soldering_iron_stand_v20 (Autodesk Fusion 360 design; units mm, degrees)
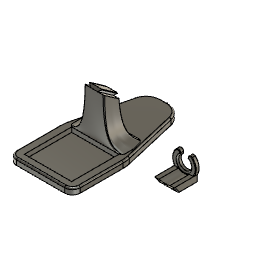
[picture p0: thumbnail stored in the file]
sketch "Sketch1" plane through (0, 0, 0) normal (0, 0, 1) x axis (1, 0, 0)
  line L1 (30.2983, -9.5) -> (-30.7017, -9.5)
  line L2 (30.2983, -70.5) -> (30.2983, -9.5)
  line L3 (-30.7017, -70.5) -> (30.2983, -70.5)
  line L4 (-30.7017, -9.5) -> (-30.7017, -70.5)
  line L5 (-31.2017, -80) -> (30.7983, -80)
  line L6 (3.9277, 80) -> (-4.3312, 80)
  line L7 (39.7519, -5.5156) -> (23.4045, 64.5446)
  line L8 (-23.808, 64.5446) -> (-40.1554, -5.5156)
  line L9 (40.7983, -70) -> (40.7983, -14.6048)
  line L10 (-41.2017, -14.6048) -> (-41.2017, -70)
  arc A1 centre (-4.3312, 60) radius 20 clockwise from (-23.808, 64.5446) to (-4.3312, 80)
  arc A2 centre (3.9277, 60) radius 20 clockwise from (3.9277, 80) to (23.4045, 64.5446)
  arc A3 centre (0.7983, -14.6048) radius 40 clockwise from (39.7519, -5.5156) to (40.7983, -14.6048)
  arc A4 centre (-1.2017, -14.6048) radius 40 clockwise from (-41.2017, -14.6048) to (-40.1554, -5.5156)
  arc A5 centre (-31.2017, -70) radius 10 clockwise from (-31.2017, -80) to (-41.2017, -70)
  arc A6 centre (30.7983, -70) radius 10 clockwise from (40.7983, -70) to (30.7983, -80)
  point P8 (-20.2017, 80)
  point P9 (19.7983, 80)
  point P10 (40.7983, -10)
  point P11 (-41.2017, -10)
  point P7 (-41.2017, -80)
  point P6 (40.7983, -80)
  point P2 (-30.7017, -9.5)
  point P3 (30.2983, -9.5)
  point P5 (-30.7017, -70.5)
  horizontal L1
  vertical L2
  horizontal L3
  vertical L4
  horizontal L5
  perpendicular L5 L9
  perpendicular L5 L10
  coincident P8 L6
  coincident P8 L8
  tangent L6 A1
  tangent L8 A1
  coincident P9 L6
  coincident P9 L7
  tangent L6 A2
  tangent L7 A2
  coincident P10 L7
  coincident P10 L9
  tangent L7 A3
  tangent L9 A3
  coincident P11 L8
  coincident P11 L10
  tangent L8 A4
  tangent L10 A4
  coincident P7 L5
  coincident P7 L10
  tangent L5 A5
  tangent L10 A5
  coincident P6 L5
  coincident P6 L9
  tangent L5 A6
  tangent L9 A6
  dimension "d1" distance P2 P3 = 61
  dimension "d2" distance P2 P5 = 61
  dimension "d7" distance P8 P9 = 40
  dimension "d9" distance P7 P11 = 70
  dimension "d11" distance P8 P11 = 90
  dimension "d12" distance P9 P10 = 90
  dimension "d13" distance P6 P7 = 82
  dimension "d14" distance P6 P10 = 70
  dimension "d15" distance P9 P10 = 21
  dimension "d16" radius A1 = 20
  dimension "d17" radius A2 = 20
  dimension "d18" radius A3 = 40
  dimension "d19" radius A4 = 40
  dimension "d20" radius A5 = 10
  dimension "d21" radius A6 = 10
  dimension "d22" distance L4 L10 = 10.5
  dimension "d23" distance L3 L5 = 9.5
extrude "Extrude1" new body sketch "Sketch1" along normal blind 8
fillet "Fillet1" radius 2
extrude "Extrude2" cut sketch "Sketch1" profile of L1 L2 L3 L4 along normal blind 10
sketch "Sketch2" plane through (0, 0, 0) normal (0, 0, 1) x axis (1, 0, 0)
  line L1 (35, -75) -> (-35, -75)
  line L2 (35, -5) -> (35, -75)
  line L3 (-35, -5) -> (35, -5)
  line L4 (-35, -75) -> (-35, -5)
  horizontal L1
  vertical L2
  horizontal L3
  vertical L4
extrude "Extrude3" add sketch "Sketch2" along normal blind 2
sketch "Sketch3" plane through (0, 0, 8) normal (0, 0, 1) x axis (-1, 0, 0)
  line L1 (30.7017, 9.5) -> (30.7017, 70.5)
  line L2 (-30.2983, 9.5) -> (30.7017, 9.5)
  line L3 (-30.2983, 70.5) -> (-30.2983, 9.5)
  line L4 (30.7017, 70.5) -> (-30.2983, 70.5)
  line L5 (-38.7983, 14.6048) -> (-38.7983, 70)
  line L6 (-21.4569, -64.0901) -> (-37.8043, 5.9701)
  line L7 (4.3312, -78) -> (-3.9277, -78)
  line L8 (38.2077, 5.9701) -> (21.8603, -64.0901)
  line L9 (39.2017, 70) -> (39.2017, 14.6048)
  line L10 (-30.7983, 78) -> (31.2017, 78)
  line L11 (-25.9962, -20.5) -> (26.3996, -20.5)
  line L12 (-33.7983, 4.5) -> (-33.7983, -3.3546)
  line L13 (29.2017, 9.5) -> (-28.7983, 9.5)
  line L14 (34.2017, -3.3546) -> (34.2017, 4.5)
  line L15 (-33.0709, -8.6994) -> (-30.8144, -16.8362)
  line L16 (33.4743, -8.6994) -> (31.2178, -16.8362)
  arc A1 centre (-30.7983, 70) radius 8 clockwise from (-38.7983, 70) to (-30.7983, 78)
  arc A2 centre (-0.7983, 14.6048) radius 38 clockwise from (-37.8043, 5.9701) to (-38.7983, 14.6048)
  arc A3 centre (-3.9277, -60) radius 18 clockwise from (-3.9277, -78) to (-21.4569, -64.0901)
  arc A4 centre (4.3312, -60) radius 18 clockwise from (21.8603, -64.0901) to (4.3312, -78)
  arc A5 centre (1.2017, 14.6048) radius 38 clockwise from (39.2017, 14.6048) to (38.2077, 5.9701)
  arc A6 centre (31.2017, 70) radius 8 clockwise from (31.2017, 78) to (39.2017, 70)
  arc A7 centre (-28.7983, 4.5) radius 5 clockwise from (-33.7983, 4.5) to (-28.7983, 9.5)
  arc A8 centre (29.2017, 4.5) radius 5 clockwise from (29.2017, 9.5) to (34.2017, 4.5)
  arc A9 centre (-13.7983, -3.3546) radius 20 clockwise from (-33.0709, -8.6994) to (-33.7983, -3.3546)
  arc A10 centre (14.2017, -3.3546) radius 20 clockwise from (34.2017, -3.3546) to (33.4743, -8.6994)
  arc A11 centre (-25.9962, -15.5) radius 5 clockwise from (-25.9962, -20.5) to (-30.8144, -16.8362)
  arc A12 centre (26.3996, -15.5) radius 5 clockwise from (31.2178, -16.8362) to (26.3996, -20.5)
  point P25 (-33.7983, -20.5)
  point P24 (34.2017, -20.5)
  point P26 (-33.7983, 9.5)
  point P27 (34.2017, 9.5)
  point P28 (-29.7983, -20.5)
  point P29 (30.2017, -20.5)
  horizontal L11
  vertical L12
  horizontal L13
  vertical L14
  coincident P25 L11
  coincident P25 L12
  coincident P24 L11
  coincident P24 L14
  coincident P26 L12
  coincident P26 L13
  tangent L12 A7
  tangent L13 A7
  coincident P27 L13
  coincident P27 L14
  tangent L13 A8
  tangent L14 A8
  equal A7 A8
  tangent L15 A9
  tangent L12 A9
  tangent L16 A10
  tangent L14 A10
  equal A9 A10
  coincident P28 L15
  coincident L11 P28
  tangent L15 A11
  tangent L11 A11
  coincident P29 L16
  coincident L11 P29
  tangent L16 A12
  tangent L11 A12
  equal A11 A12
  dimension "d32" distance P26 P27 = 68
  dimension "d33" distance L1 L14 = 3.5
  dimension "d34" distance P24 P27 = 30
  dimension "d35" distance L2 L11 = 30
  dimension "d36" distance P25 P28 = 4
  dimension "d37" angle L11 L15 = 74.5
  dimension "d38" distance P24 P29 = 4
  dimension "d39" angle L11 L16 = 74.5
  dimension "d40" radius A7 = 5
  dimension "d41" radius A9 = 20
  dimension "d42" radius A11 = 5
work_plane "WorkPlane1" sketch "Sketch3" AlongDistance 61
sketch "Sketch4" plane through (-0.2017, 0, 69) normal (0, 0, 1) x axis (1, 0, 0)
  line L1 (-14, -9.5) -> (11, -9.5)
  line L2 (-14, 10.5) -> (-14, -9.5)
  line L3 (11, 10.5) -> (-14, 10.5)
  line L4 (11, -9.5) -> (11, 10.5)
  line L5 (-29, -9.5) -> (29, -9.5)
  line L6 (34, -4.5) -> (34, 3.3546)
  point P2 (11, -9.5)
  point P3 (-14, -9.5)
  point P5 (11, 10.5)
  horizontal L1
  vertical L2
  horizontal L3
  vertical L4
  dimension "d44" distance P2 P3 = 25
  dimension "d45" distance P2 P5 = 20
  dimension "d47" distance L3 L5 = 20
  dimension "d48" distance L4 L6 = 23
loft "Loft2" sketch "Sketch4" + "Sketch3" Start Weight 2.5 Start TakeOff Angle 0
sketch "Sketch7" plane through (0, 0, 69) normal (0, 0, 1) x axis (-1, 0, 0)
  line L1 (15.2017, 9.5) -> (-11.7983, 9.5)
  line L2 (15.2017, -11.5) -> (15.2017, 9.5)
  line L3 (-11.7983, -11.5) -> (15.2017, -11.5)
  line L4 (-11.7983, 9.5) -> (-11.7983, -11.5)
  line L5 (-10.7983, -10.5) -> (14.2017, -10.5)
  line L6 (14.2017, 9.5) -> (-10.7983, 9.5)
  line L7 (14.2017, -10.5) -> (14.2017, 9.5)
  line L8 (-10.7983, 9.5) -> (-10.7983, -10.5)
  horizontal L1
  vertical L2
  horizontal L3
  vertical L4
  dimension "d61" distance L3 L5 = 1
  dimension "d63" distance L2 L7 = 1
  dimension "d64" distance L4 L8 = 1
  dimension "d87" distance L1 L3 = 21
extrude "Extrude7" new body sketch "Sketch7" along normal blind 15
sketch "Sketch13" plane through (-15.2017, 0, 0) normal (-1, 0, 0) x axis (0, -1, 0)
  line L1 (9.5, 69) -> (-11.5, 69)
  line L2 (9.5, 84) -> (9.5, 69)
  line L3 (-11.5, 84) -> (9.5, 84)
  line L4 (-11.5, 69) -> (-11.5, 84)
  line L5 (-10.8385, 69) -> (9.5, 69)
  line L6 (-10.8385, 54.7588) -> (-10.8385, 69)
  line L7 (9.5, 69) -> (-10.8385, 54.7588)
  point P6 (9.5, 69)
  point P7 (-10.8385, 69)
  point P8 (9.5, 69)
  coincident L1 P6
  coincident L1 P7
  coincident P6 P8
  perpendicular L1 L6
  dimension "d82" angle L5 L7 = 35
extrude "Extrude13" cut sketch "Sketch13" profile of L1 L5 L6 L7 against normal blind 27
sketch "Sketch16" plane through (-15.2017, 0, 0) normal (-1, 0, 0) x axis (0, -1, 0)
  line L1 (9.5, 69) -> (-11.5, 69)
  line L2 (9.5, 84) -> (9.5, 69)
  line L3 (-11.5, 84) -> (9.5, 84)
  line L4 (-11.5, 69) -> (-11.5, 84)
  line L5 (9.5, 84) -> (9.5, 69)
  line L6 (-1.0031, 84) -> (9.5, 69)
  line L7 (-1.0031, 84) -> (9.5, 84)
  point P3 (9.5, 69)
  point P6 (9.5, 69)
  point P4 (9.5, 84)
  point P7 (9.5, 84)
  point P8 (-1.0031, 84)
  coincident P3 P6
  coincident P4 P7
  coincident L3 P8
  dimension "d97" angle L5 L6 = 35
extrude "Extrude14" cut sketch "Sketch16" profile of L2 L3 L5 L6 L7 against normal blind 27
sketch "Sketch17" plane through (0, -38.794, 27.1638) normal (0, -0.8192, 0.5736) x axis (1, 0, 0)
  line L1 (-15.2017, 51.0725) -> (-15.2017, 69.3841)
  line L2 (11.7983, 51.0725) -> (-15.2017, 51.0725)
  line L3 (11.7983, 69.3841) -> (11.7983, 51.0725)
  line L4 (-15.2017, 69.3841) -> (11.7983, 69.3841)
  line L5 (6.7983, 51.0725) -> (-10.2017, 51.0725)
  line L6 (2.7983, 47.0725) -> (6.7983, 51.0725)
  line L7 (-6.2017, 47.0725) -> (-10.2017, 51.0725)
  line L8 (2.7983, 47.0725) -> (-6.2017, 47.0725)
  line L9 (11.7983, 51.0725) -> (-15.2017, 51.0725)
  line L10 (11.7983, 47.0725) -> (11.7983, 51.0725)
  line L11 (-15.2017, 47.0725) -> (11.7983, 47.0725)
  line L12 (-15.2017, 51.0725) -> (-15.2017, 47.0725)
  point P6 (-10.2017, 51.0725)
  point P7 (6.7983, 51.0725)
  point P3 (-15.2017, 51.0725)
  point P10 (-15.2017, 51.0725)
  point P4 (11.7983, 51.0725)
  point P9 (-6.2017, 47.0725)
  point P8 (2.7983, 47.0725)
  point P11 (11.7983, 51.0725)
  coincident L2 P6
  coincident L2 P7
  perpendicular L1 L5
  horizontal L9
  vertical L10
  horizontal L11
  vertical L12
  coincident P3 P10
  dimension "d100" distance P4 P7 = 5
  dimension "d101" distance P6 P7 = 17
  dimension "d102" angle L5 L6 = 45
  dimension "d103" angle L5 L7 = 45
  dimension "d104" distance L5 P9 = 4
  dimension "d105" distance L5 P8 = 4
  dimension "d106" distance P10 P11 = 27
  dimension "d107" distance L9 L11 = 4
extrude "Extrude15" cut sketch "Sketch17" profile of L2 L6 L7 L9 L10 L11 L12 against normal blind 28
sketch "Sketch18" plane through (0, 29.294, 41.8362) normal (0, 0.5736, 0.8192) x axis (-1, 0, 0)
  line L1 (10.2017, 47.3587) -> (10.2017, 22.8335)
  line L2 (-6.7983, 47.3587) -> (10.2017, 47.3587)
  line L3 (-6.7983, 22.8335) -> (-6.7983, 47.3587)
  curve K1 (-6.7983, 22.8335) -> (10.2017, 22.8335)
  line L4 (10.2017, 47.3587) -> (-6.7983, 47.3587)
  line L5 (10.2017, 44.5507) -> (10.2017, 47.3587)
  line L6 (-6.7983, 44.5507) -> (10.2017, 44.5507)
  line L7 (-6.7983, 47.3587) -> (-6.7983, 44.5507)
  point P4 (-6.7983, 47.3587)
  point P6 (-6.7983, 47.3587)
  point P7 (10.2017, 47.3587)
  point P9 (-6.7983, 44.5507)
  horizontal L4
  vertical L5
  horizontal L6
  vertical L7
  coincident P4 P6
  dimension "d110" distance P6 P7 = 17
  dimension "d111" distance P6 P9 = 2.808
extrude "Extrude17" cut sketch "Sketch18" profile of L1 L2 L3 L4 L5 L6 L7 against normal blind 4
sketch "Sketch22" plane through (0, 0, 0) normal (0, 0, 1) x axis (1, 0, 0)
  line L1 (103.5444, 18.6577) -> (78.5444, 18.6577)
  line L2 (103.5444, -11.6363) -> (103.5444, 18.6577)
  line L3 (78.5444, -11.6363) -> (103.5444, -11.6363)
  line L4 (78.5444, 18.6577) -> (78.5444, -11.6363)
  point P2 (78.5444, 18.6577)
  point P3 (103.5444, 18.6577)
  point P5 (78.5444, -11.6363)
  horizontal L1
  vertical L2
  horizontal L3
  vertical L4
  dimension "d122" distance P2 P3 = 25
  dimension "d123" distance P2 P5 = 30.294 (= "24.692 mm + 5.602 mm")
extrude "Extrude18" new body sketch "Sketch22" along normal blind 8
sketch "Sketch23" plane through (0, -11.6363, 0) normal (0, -1, 0) x axis (1, 0, 0)
  line L1 (103.5444, 0) -> (78.5444, 0)
  line L2 (103.5444, 8) -> (103.5444, 0)
  line L3 (78.5444, 8) -> (103.5444, 8)
  line L4 (78.5444, 0) -> (78.5444, 8)
  line L5 (99.7484, 4.096) -> (95.6524, 0)
  line L6 (82.3404, 4.096) -> (86.4364, 0)
  line L7 (99.7484, 4.096) -> (82.3404, 4.096)
  line L8 (95.6524, 0) -> (86.4364, 0)
  point P6 (95.6524, 0)
  point P8 (86.4364, 0)
  point P7 (99.7484, 4.096)
  point P9 (82.3404, 4.096)
  coincident L1 P6
  coincident L1 P8
  parallel L3 L7
  dimension "d126" distance P7 P9 = 17.408
  dimension "d127" distance L2 P7 = 3.796
  dimension "d128" distance P6 L7 = 4.096
  dimension "d129" angle L6 L7 = 45
  dimension "d130" angle L5 L7 = 45
extrude "Extrude19" cut sketch "Sketch23" profile of L1 L5 L6 L7 L8 against normal blind 31
sketch "Sketch25" plane through (0, 18.6577, 0) normal (0, 1, 0) x axis (-1, 0, 0)
  line L1 (-78.5444, 0) -> (-86.4364, 0)
  line L2 (-78.5444, 8) -> (-78.5444, 0)
  line L3 (-103.5444, 8) -> (-78.5444, 8)
  line L4 (-103.5444, 0) -> (-103.5444, 8)
  line L5 (-86.4364, 0) -> (-82.3404, 4.096)
  line L6 (-95.6524, 0) -> (-103.5444, 0)
  line L7 (-99.7484, 4.096) -> (-95.6524, 0)
  line L8 (-82.3404, 4.096) -> (-99.7484, 4.096)
  circle C1 centre (-91.0444, 16.55) radius 11.1
  circle C2 centre (-91.0444, 16.55) radius 15.1444
  circle C3 centre (-91.0444, 16.55) radius 8.5
  point P4 (-78.5444, 8)
  point P7 (-91.0444, 16.55)
  concentric C1 C2
  coincident P4 C2
  concentric C1 C3
  dimension "d137" diameter C1 = 22.2
  dimension "d139" distance L2 P7 = 12.5
  dimension "d144" diameter C3 = 17
  dimension "d225" distance L3 P7 = 8.55
extrude "Extrude26" cut sketch "Sketch25" profile of L3 C1 against normal blind 30.5
extrude "Extrude27" add sketch "Sketch25" profile of L3 C1 C2 C3 against normal blind 5
sketch "Sketch27" plane through (0, 18.6577, 0) normal (0, 1, 0) x axis (-1, 0, 0)
  line L1 (-103.5444, 0) -> (-103.5444, 8)
  line L2 (-95.6524, 0) -> (-103.5444, 0)
  line L3 (-78.5444, 8) -> (-78.5444, 0)
  line L4 (-82.5444, 16.55) -> (-99.5444, 16.55)
  line L5 (-86.0444, 23.4239) -> (-96.0444, 23.4239)
  line L6 (-96.0444, 31.6944) -> (-96.0444, 23.4239)
  line L7 (-86.0444, 31.6944) -> (-96.0444, 31.6944)
  line L8 (-86.0444, 23.4239) -> (-86.0444, 31.6944)
  line L9 (-99.7484, 4.096) -> (-95.6524, 0)
  line L10 (-82.3404, 4.096) -> (-99.7484, 4.096)
  line L11 (-86.4364, 0) -> (-82.3404, 4.096)
  line L12 (-78.5444, 0) -> (-86.4364, 0)
  circle C1 centre (-91.0444, 16.55) radius 8.5
  arc A1 centre (-91.0444, 16.55) radius 15.1444 clockwise from (-103.5444, 8) to (-78.5444, 8)
  point P8 (-99.5444, 16.55)
  point P9 (-82.5444, 16.55)
  point P2 (-91.0444, 16.55)
  point P10 (-96.0444, 23.4239)
  point P11 (-86.0444, 23.4239)
  coincident C1 P8
  coincident C1 P9
  horizontal L4
  coincident P2 L4
  coincident C1 P10
  coincident C1 P11
  parallel L4 L5
  perpendicular L5 L6
  perpendicular L6 L7
  perpendicular L5 L8
  dimension "d169" distance P9 P11 = 3.5
extrude "Extrude32" cut sketch "Sketch27" profile of C1 A1 L6 L8 against normal blind 5
chamfer "Chamfer4" distance 1.6 distance 1.8
fillet "Fillet13" radius 3.06
fillet "Fillet15" radius 0.7
sketch "Sketch28" plane through (103.5444, 0, 0) normal (1, 0, 0) x axis (0, 1, 0)
  line L1 (18.6577, 0) -> (-11.6363, 0)
  line L2 (18.6577, 9.3119) -> (18.6577, 0)
  curve K1 (17.9577, 8) -> (18.6577, 9.3119)
  line L3 (14.3577, 8) -> (17.9577, 8)
  line L4 (-11.6363, 8) -> (14.3577, 8)
  line L5 (-6.0343, 0) -> (-11.6363, 0)
  line L6 (-11.6363, 8) -> (-6.0343, 0)
  line L7 (-11.6363, 0) -> (-11.6363, 8)
  point P2 (-11.6363, 0)
  point P8 (-11.6363, 0)
  point P7 (-11.6363, 8)
  point P10 (-11.6363, 8)
  point P9 (-6.0343, 0)
  coincident P2 P8
  parallel L1 L5
  coincident P7 P10
  dimension "d196" distance P8 P9 = 5.602
extrude "Extrude33" cut sketch "Sketch28" profile of L1 L5 L6 L7 against normal blind 25
sketch "Sketch29" plane through (103.5444, 0, 0) normal (1, 0, 0) x axis (0, 1, 0)
  line L1 (-6.0343, 0) -> (-11.6363, 8)
  line L2 (18.6577, 0) -> (-6.0343, 0)
  line L3 (18.6577, 9.3119) -> (18.6577, 0)
  curve K1 (17.9577, 8) -> (18.6577, 9.3119)
  line L4 (14.3577, 8) -> (17.9577, 8)
  line L5 (-11.6363, 8) -> (14.3577, 8)
  line L6 (-6.0343, 5) -> (-6.0343, 0)
  line L7 (-9.5356, 5) -> (-6.0343, 5)
  line L8 (-9.5356, 5) -> (-6.0343, 0)
  point P3 (-6.0343, 0)
  point P8 (-6.0343, 0)
  point P10 (-9.5356, 5)
  coincident P3 P8
  perpendicular L2 L6
  coincident L1 P10
  perpendicular L6 L7
extrude "Extrude34" add sketch "Sketch29" profile of L1 L6 L7 L8 against normal blind 25
extrude "Extrude35" add of existing geometry blind -24.627
fillet "Fillet22" radius 1
fillet "Fillet23" radius 0.4
fillet "Fillet24" radius 1
fillet "Fillet25" radius 0.5
fillet "Fillet26" radius 0.4
extrude "Extrude36" cut of existing geometry blind -0.0412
